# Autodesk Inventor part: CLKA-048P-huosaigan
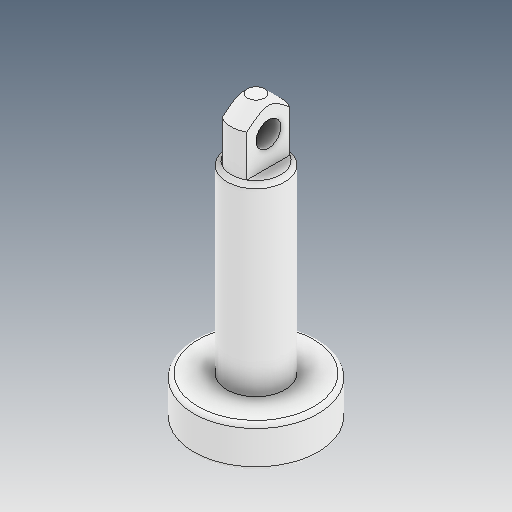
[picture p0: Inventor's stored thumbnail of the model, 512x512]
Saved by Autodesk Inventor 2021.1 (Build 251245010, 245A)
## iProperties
Created: 2021-06
Part Number: CLKA-048P-huosaigan
Material: Ogólny
Document SubType Name: Modeling
Designer: user
Density: 1 g/cm^3
Appearance: Domyślna
Author: user
Revision Number: ÈÎºÎ
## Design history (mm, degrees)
feature "ÇÐ³ý-À­Éì2"
node "Bryła1"
